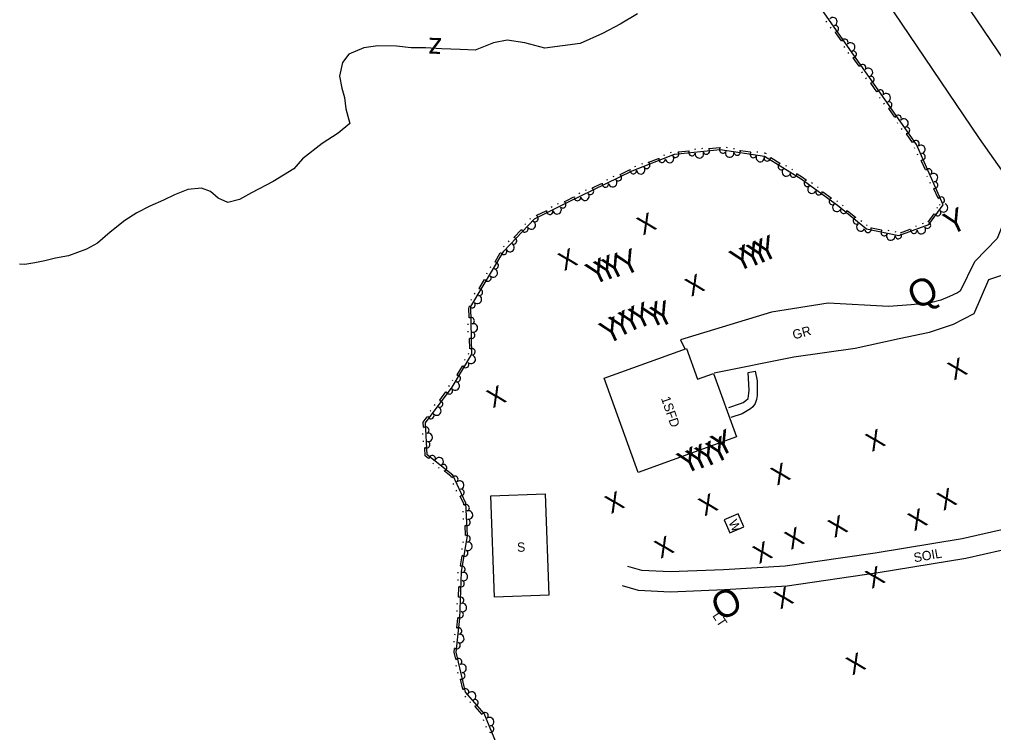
# Model space of a CAD drawing. Extents: x 2030130 to 2036320, y 723205 to 762423.
# Drawn here: x 2032662.3 to 2033049.3, y 761484.7 to 761768 of the extents above; entities that cross this region are included whole.
import ezdxf

# ---------------------------------------------------------------- set-up
doc = ezdxf.new("R2010")
doc.units = 0
for name, color, linetype in [('Draft_Station Cardinal Points', 7, 'Continuous'), ('Draft_Station Labels Major', 7, 'Continuous'), ('Draft_Station Tics Major', 7, 'Continuous'), ('Exist Terrain Model Ground Surface', 7, 'Continuous'), ('Old_Level_15', 7, 'Continuous'), ('Old_Level_23', 7, 'Continuous'), ('Old_Level_28', 7, 'Continuous'), ('Old_Level_29', 7, 'Continuous'), ('Prop Alignment Horizontal', 7, 'Continuous')]:
    doc.layers.add(name, color=color, linetype=linetype)

msp = doc.modelspace()

# ---------------------------------------------------------------- linework, layer by layer
at = {"layer": 'Draft_Station Labels Major'}
msp.add_line((2033036.26, 761660.15), (2033041.96, 761671.86), dxfattribs=at)
for points in [[(2033317.86, 761363.04), (2033290.43, 761403.19), (2033260.47, 761446.88), (2033232.75, 761487.83), (2033204.6, 761528.87), (2033176.73, 761570.42), (2033148.96, 761611.47), (2033120.54, 761652.92), (2033093.45, 761693.44), (2033064.45, 761735.88), (2033037.38, 761775.77), (2033009.06, 761817.74)], [(2032987.95, 761803.12), (2033043.65, 761720.79), (2033056.64, 761702.34), (2033057.8, 761696.58), (2033076.72, 761668.89), (2033082.75, 761662.9), (2033099.45, 761638.44), (2033127.47, 761597.33), (2033155.33, 761556.18), (2033183.52, 761515.12), (2033211.27, 761473.78), (2033239.33, 761432.83), (2033268.78, 761389.51), (2033297.27, 761347.85)], [(2033056.71, 761695.8), (2033050.78, 761681.05), (2033041.96, 761671.86)], [(2033047.49, 761664.65), (2033056.57, 761667.76), (2033074.01, 761668.5)], [(2033033.48, 761646.95), (2033041.61, 761651.18), (2033047.49, 761664.65)], [(2033036.26, 761660.15), (2033034.98, 761659.46), (2033031.83, 761657.97), (2033028.37, 761656.53), (2033024.32, 761655.42), (2033020.58, 761655.09), (2033016.67, 761654.67), (2033007.62, 761654.04), (2032983.56, 761655.29), (2032961.1, 761651.78), (2032924.92, 761640.71), (2032926.73, 761637.14)], [(2032938.32, 761627.58), (2032970.02, 761634.01), (2032994.32, 761637.43), (2033011.86, 761641.33), (2033023.86, 761643.74), (2033033.48, 761646.95)], [(2033094.5, 761577.75), (2033081.76, 761573.32), (2033064.34, 761567.87), (2033036.86, 761561.74), (2033002.27, 761556.02), (2032966.52, 761550.81), (2032942.02, 761549.37), (2032920.85, 761548.52), (2032909.53, 761549.08), (2032903.98, 761550.63)], [(2033097.11, 761570.23), (2033084.26, 761565.76), (2033066.4, 761560.17), (2033038.38, 761553.92), (2033003.49, 761548.15), (2032967.33, 761542.88), (2032942.41, 761541.42), (2032920.81, 761540.55), (2032908.24, 761541.17), (2032901.84, 761542.96)]]:
    msp.add_lwpolyline(points, dxfattribs=at)
at = {"layer": 'Draft_Station Tics Major'}
for points in [[(2032852.15, 761479.7), (2032846.89, 761492.29), (2032839.53, 761500.8), (2032835.8, 761516.7), (2032837.3, 761530.01), (2032837.88, 761548.53), (2032840.35, 761563.07), (2032839.64, 761575.83), (2032834.44, 761586.98), (2032824.33, 761595.03), (2032823.56, 761607.79), (2032834.21, 761621.99), (2032842.05, 761635.05), (2032841.62, 761653.99), (2032854.71, 761675.98), (2032866.89, 761688.81), (2032879.86, 761695.28), (2032905.7, 761707.84), (2032922.57, 761714.44), (2032940.67, 761716.34), (2032958.31, 761713.76), (2032972.94, 761704.72), (2032987.28, 761694.28), (2032998.83, 761684.81), (2033011.7, 761682.14), (2033023.69, 761686.54), (2033029.34, 761694.39), (2033018.75, 761718.29), (2032987.59, 761762.73), (2032957.8, 761805.4)], [(2032983.12, 761766.97), (2032982.89, 761767.31)], [(2032984.76, 761764.62), (2032984.53, 761764.96)], [(2032988.86, 761759.48), (2032986.91, 761762.26), (2032986.51, 761762.84)], [(2032990.18, 761756.89), (2032989.94, 761757.23)], [(2032991.82, 761754.54), (2032991.59, 761754.88)], [(2032995.93, 761749.4), (2032993.57, 761752.76)], [(2032997.24, 761746.82), (2032997, 761747.15)], [(2032998.89, 761744.47), (2032998.65, 761744.8)], [(2033002.99, 761739.33), (2033000.64, 761742.69)], [(2033004.3, 761736.74), (2033004.07, 761737.08)], [(2033005.95, 761734.39), (2033005.72, 761734.73)], [(2033010.05, 761729.26), (2033007.7, 761732.61)], [(2033011.37, 761726.67), (2033011.13, 761727.01)], [(2033013.02, 761724.32), (2033012.78, 761724.65)], [(2033017.12, 761719.18), (2033014.76, 761722.54)], [(2032933.47, 761716.82), (2032933.87, 761716.87)], [(2032936.36, 761716.72), (2032940.44, 761717.15)], [(2032943.14, 761717.22), (2032943.55, 761717.17)], [(2033018.11, 761716.69), (2033017.94, 761717.07)], [(2032918.31, 761714.1), (2032918.7, 761714.25)], [(2032920.99, 761715.15), (2032921.37, 761715.29)], [(2032924.13, 761715.43), (2032928.21, 761715.86)], [(2032930.61, 761716.52), (2032931.02, 761716.57)], [(2032945.98, 761716.81), (2032946.39, 761716.75)], [(2032948.76, 761715.99), (2032952.82, 761715.39)], [(2032955.31, 761715.44), (2032955.72, 761715.38)], [(2032958.16, 761715.02), (2032958.74, 761714.94), (2032959.02, 761714.77)], [(2032960.9, 761713.12), (2032964.39, 761710.97)], [(2033019.27, 761714.07), (2033019.11, 761714.44)], [(2032906.86, 761709.61), (2032907.24, 761709.76)], [(2032909.53, 761710.66), (2032909.91, 761710.81)], [(2032912.35, 761711.33), (2032916.17, 761712.82)], [(2032966.69, 761710.02), (2032967.04, 761709.81)], [(2033022.31, 761708.23), (2033020.64, 761711.98)], [(2032898.23, 761705.58), (2032898.6, 761705.76)], [(2032900.99, 761706.46), (2032904.68, 761708.26)], [(2032969.14, 761708.51), (2032969.48, 761708.3)], [(2032971.36, 761706.65), (2032973.39, 761705.4), (2032974.83, 761704.35)], [(2033023.09, 761705.44), (2033022.93, 761705.82)], [(2032889.93, 761701.08), (2032893.61, 761702.88)], [(2032895.65, 761704.32), (2032896.02, 761704.5)], [(2032977.06, 761703.24), (2032977.39, 761703)], [(2032979.38, 761701.55), (2032979.71, 761701.31)], [(2033024.26, 761702.82), (2033024.09, 761703.19)], [(2032884.58, 761698.94), (2032884.95, 761699.12)], [(2032887.17, 761700.2), (2032887.53, 761700.38)], [(2032981.46, 761699.53), (2032984.77, 761697.11)], [(2033027.29, 761696.98), (2033025.63, 761700.73)], [(2032873.54, 761693.5), (2032873.9, 761693.68)], [(2032876.11, 761694.78), (2032876.47, 761694.96)], [(2032878.86, 761695.69), (2032879.5, 761696.01), (2032882.55, 761697.5)], [(2032987.01, 761696), (2032987.34, 761695.76)], [(2032989.33, 761694.19), (2032989.64, 761693.93)], [(2033028.08, 761694.19), (2033027.91, 761694.57)], [(2032867.85, 761690.21), (2032871.52, 761692.03)], [(2032991.29, 761692.05), (2032994.46, 761689.45)], [(2033023.35, 761687.48), (2033025.75, 761690.81)], [(2033026.85, 761693.05), (2033027.09, 761693.38)], [(2032863.06, 761686.57), (2032863.34, 761686.86)], [(2032865.04, 761688.65), (2032865.32, 761688.95)], [(2032996.62, 761688.21), (2032996.94, 761687.95)], [(2032998.84, 761686.39), (2032999.16, 761686.13)], [(2033018.41, 761685.91), (2033018.79, 761686.05)], [(2033021.1, 761686.9), (2033021.49, 761687.04)], [(2032858.84, 761681.52), (2032861.67, 761684.5)], [(2033000.83, 761685.23), (2033004.85, 761684.4)], [(2033007.34, 761684.3), (2033007.74, 761684.22)], [(2033010.15, 761683.72), (2033010.55, 761683.63)], [(2033012.39, 761683.26), (2033016.24, 761684.68)], [(2032856.57, 761679.72), (2032856.85, 761680.02)], [(2032851.23, 761671.73), (2032853.33, 761675.25)], [(2032854.59, 761677.64), (2032854.88, 761677.94)], [(2032847.94, 761667.01), (2032848.15, 761667.36)], [(2032849.4, 761669.47), (2032849.61, 761669.82)], [(2032844.93, 761661.16), (2032847.03, 761664.68)], [(2032843.11, 761658.9), (2032843.32, 761659.25)], [(2032841.64, 761656.44), (2032841.85, 761656.79)], [(2032840.9, 761649.52), (2032840.8, 761653.62)], [(2032840.55, 761646.64), (2032840.54, 761647.05)], [(2032840.62, 761643.77), (2032840.61, 761644.18)], [(2032841.18, 761637.22), (2032841.09, 761641.32)], [(2032839.17, 761632.64), (2032839.38, 761632.99)], [(2032840.65, 761635.1), (2032840.86, 761635.45)], [(2032836.15, 761626.8), (2032838.26, 761630.32)], [(2032834.32, 761624.55), (2032834.53, 761624.91)], [(2032832.86, 761622.23), (2032833.1, 761622.56)], [(2032829.25, 761616.74), (2032831.71, 761620.02)], [(2032825.48, 761612.39), (2032825.72, 761612.72)], [(2032827.2, 761614.69), (2032827.45, 761615.01)], [(2032822.85, 761606.01), (2032822.73, 761608.04), (2032824.33, 761610.17)], [(2032822.61, 761603.12), (2032822.59, 761603.53)], [(2032822.79, 761600.25), (2032822.76, 761600.66)], [(2032824.81, 761593.61), (2032823.54, 761594.62), (2032823.34, 761597.82)], [(2032826.8, 761591.5), (2032826.48, 761591.76)], [(2032829.04, 761589.71), (2032828.72, 761589.96)], [(2032833.97, 761586.06), (2032833.78, 761586.46), (2032831.22, 761588.5)], [(2032834.81, 761583.28), (2032834.64, 761583.65)], [(2032836.02, 761580.68), (2032835.85, 761581.05)], [(2032838.86, 761575.15), (2032838.83, 761575.63), (2032837.43, 761578.62)], [(2032838.61, 761572.26), (2032838.59, 761572.67)], [(2032838.77, 761569.39), (2032838.75, 761569.8)], [(2032839.52, 761563.05), (2032839.53, 761563.11), (2032839.32, 761566.96)], [(2032838.63, 761560.29), (2032838.7, 761560.69)], [(2032837.46, 761550.92), (2032838.15, 761554.96)], [(2032838.15, 761557.46), (2032838.22, 761557.86)], [(2032836.64, 761547.98), (2032836.65, 761548.39)], [(2032836.55, 761545.11), (2032836.56, 761545.52)], [(2032836.75, 761538.54), (2032836.88, 761542.64)], [(2032836.25, 761535.69), (2032836.27, 761536.1)], [(2032836.16, 761532.82), (2032836.17, 761533.22)], [(2032836.06, 761526.33), (2032836.49, 761530.07), (2032836.5, 761530.34)], [(2032835.33, 761523.53), (2032835.38, 761523.93)], [(2032835.01, 761520.67), (2032835.06, 761521.08)], [(2032835.62, 761513.88), (2032834.97, 761516.65), (2032835.14, 761518.18)], [(2032835.87, 761510.99), (2032835.78, 761511.39)], [(2032836.53, 761508.2), (2032836.44, 761508.6)], [(2032838.43, 761501.9), (2032837.49, 761505.9)], [(2032839.61, 761498.83), (2032839.34, 761499.14)], [(2032841.49, 761496.66), (2032841.22, 761496.97)], [(2032846.09, 761491.96), (2032843.41, 761495.06)], [(2032846.76, 761489.42), (2032846.6, 761489.8)], [(2032847.86, 761486.77), (2032847.71, 761487.15)]]:
    msp.add_lwpolyline(points, dxfattribs=at)
for centre, radius, start, end in [((2032985.51, 761767.14), 1.69, 290.8826, 138.9551), ((2032986.48, 761764.31), 1.3, 265.6873, 106.4839), ((2032990.24, 761758.94), 1.3, 323.4732, 164.2697), ((2032992.56, 761757.06), 1.69, 291.002, 139.0744), ((2032993.54, 761754.24), 1.3, 265.8067, 106.6033), ((2032997.31, 761748.87), 1.3, 323.4732, 164.2697), ((2032999.62, 761746.99), 1.69, 291.002, 139.0744), ((2033000.6, 761744.17), 1.3, 265.8067, 106.6033), ((2033004.37, 761738.79), 1.3, 323.4732, 164.2697), ((2033006.69, 761736.91), 1.69, 291.002, 139.0744), ((2033007.67, 761734.09), 1.3, 265.8067, 106.6033), ((2033011.43, 761728.72), 1.3, 323.4732, 164.2697), ((2033013.75, 761726.84), 1.69, 291.002, 139.0744), ((2033014.73, 761724.02), 1.3, 265.8067, 106.6033), ((2032941.75, 761716.19), 1.3, 132.4304, 333.227), ((2033018.5, 761718.65), 1.3, 323.4732, 164.2697), ((2033020.48, 761716.4), 1.69, 279.8666, 127.939), ((2032920.59, 761712.79), 1.69, 187.3345, 35.407), ((2032922.99, 761714.49), 1.3, 204.4346, 45.2312), ((2032929.52, 761715.17), 1.3, 146.7682, 347.5647), ((2032932.46, 761714.66), 1.69, 171.9634, 20.0359), ((2032935.23, 761715.77), 1.3, 204.4346, 45.2312), ((2032944.47, 761714.96), 1.69, 157.6257, 5.6982), ((2032947.43, 761715.35), 1.3, 190.0969, 30.8935), ((2032953.92, 761714.4), 1.3, 132.4304, 333.227), ((2032956.64, 761713.17), 1.69, 157.6257, 5.6982), ((2032959.42, 761713.07), 1.3, 166.7062, 7.5028), ((2033020.9, 761713.44), 1.3, 254.6713, 95.4678), ((2032909.13, 761708.3), 1.69, 187.3345, 35.407), ((2032911.51, 761710.11), 1.3, 219.8057, 60.6022), ((2032917.62, 761712.5), 1.3, 162.1392, 2.9358), ((2032965, 761709.62), 1.3, 109.0398, 309.8363), ((2032900.24, 761705.19), 1.3, 224.3666, 65.1631), ((2032906.16, 761708.02), 1.3, 162.1392, 2.9358), ((2032967.01, 761707.42), 1.69, 134.235, 342.3075), ((2032969.88, 761706.6), 1.3, 166.7062, 7.5028), ((2033023.55, 761707.44), 1.3, 312.3377, 153.1343), ((2033025.47, 761705.15), 1.69, 279.8666, 127.939), ((2032895.08, 761702.68), 1.3, 166.7001, 7.4967), ((2032898.02, 761703.19), 1.69, 191.8954, 39.9678), ((2032975.34, 761702.97), 1.3, 104.7179, 305.5145), ((2032977.18, 761700.61), 1.69, 129.9132, 337.9857), ((2033025.88, 761702.19), 1.3, 254.6713, 95.4678), ((2032884.02, 761697.3), 1.3, 166.7001, 7.4967), ((2032886.96, 761697.81), 1.69, 191.8954, 39.9678), ((2032889.18, 761699.81), 1.3, 224.3666, 65.1631), ((2032979.98, 761699.59), 1.3, 162.3844, 3.181), ((2032878.12, 761694.41), 1.3, 224.926, 65.7226), ((2032985.29, 761695.73), 1.3, 104.7179, 305.5145), ((2032987.07, 761693.38), 1.69, 126.6347, 334.7072), ((2033028.54, 761696.19), 1.3, 312.3377, 153.1343), ((2033029.48, 761693.18), 1.69, 220.2362, 68.3087), ((2032867.11, 761688.92), 1.3, 224.926, 65.7226), ((2032872.98, 761691.85), 1.3, 167.2596, 8.0561), ((2032875.92, 761692.4), 1.69, 192.4548, 40.5273), ((2032989.81, 761692.2), 1.3, 159.1059, 359.9025), ((2033027.13, 761691.33), 1.3, 195.0409, 35.8375), ((2032865.68, 761686.34), 1.69, 212.4703, 60.5428), ((2032994.89, 761688.04), 1.3, 101.4395, 302.236), ((2032996.59, 761685.59), 1.69, 126.6347, 334.7072), ((2033023.07, 761686.31), 1.3, 218.6129, 59.4095), ((2032863.11, 761684.83), 1.3, 187.275, 28.0716), ((2032999.46, 761684.68), 1.3, 186.6995, 27.496), ((2033005.89, 761683.34), 1.3, 129.033, 329.8296), ((2033008.53, 761681.96), 1.69, 154.2283, 2.3008), ((2033011.51, 761682.18), 1.3, 186.6995, 27.496), ((2033017.68, 761684.33), 1.3, 160.9465, 1.743), ((2033020.65, 761684.55), 1.69, 186.1417, 34.2142), ((2032857.21, 761677.42), 1.69, 212.4703, 60.5428), ((2032858.59, 761680.07), 1.3, 244.9415, 85.7381), ((2032854.66, 761675.89), 1.3, 199.9877, 40.7843), ((2032851.3, 761670.25), 1.3, 257.6542, 98.4507), ((2032850.54, 761667.36), 1.69, 225.183, 73.2555), ((2032848.36, 761665.32), 1.3, 199.9877, 40.7843), ((2032845.01, 761659.68), 1.3, 257.6542, 98.4507), ((2032842.07, 761654.75), 1.3, 199.9877, 40.7843), ((2032844.24, 761656.79), 1.69, 225.183, 73.2555), ((2032841.75, 761648.31), 1.3, 289.7569, 130.5535), ((2032841.88, 761642.57), 1.3, 232.0904, 72.887), ((2032842.63, 761645.46), 1.69, 257.2857, 105.3582), ((2032842.03, 761636.01), 1.3, 289.7569, 130.5535), ((2032839.59, 761630.95), 1.3, 199.7883, 40.5849), ((2032841.78, 761632.99), 1.69, 224.9836, 73.0561), ((2032835.44, 761622.44), 1.69, 224.9836, 73.0561), ((2032836.22, 761625.33), 1.3, 257.4548, 98.2514), ((2032833.1, 761620.51), 1.3, 193.9023, 34.6989), ((2032829.17, 761615.26), 1.3, 251.5688, 92.3653), ((2032828.1, 761612.47), 1.69, 219.0976, 67.1701), ((2032825.72, 761610.67), 1.3, 193.9023, 34.6989), ((2032823.74, 761604.83), 1.3, 291.8945, 132.6911), ((2032824.73, 761602.01), 1.69, 259.4233, 107.4958), ((2032824.09, 761599.1), 1.3, 234.228, 75.0246), ((2032826.28, 761593.48), 1.3, 339.9007, 180.6972), ((2032829.04, 761592.34), 1.69, 307.4295, 155.502), ((2032830.77, 761589.91), 1.3, 282.2342, 123.0308), ((2032835.23, 761585.29), 1.3, 313.4267, 154.2233), ((2032837.19, 761583.03), 1.69, 280.9555, 129.028), ((2032837.66, 761580.08), 1.3, 255.7602, 96.5568), ((2032839.75, 761573.97), 1.3, 291.6309, 132.4275), ((2032840.72, 761571.14), 1.69, 259.1597, 107.2322), ((2032840.07, 761568.23), 1.3, 233.9644, 74.761), ((2032840.12, 761561.7), 1.3, 278.7913, 119.5879), ((2032840.45, 761558.73), 1.69, 246.3201, 94.3926), ((2032839.16, 761556.04), 1.3, 221.1248, 61.9214), ((2032838.06, 761549.57), 1.3, 278.7913, 119.5879), ((2032838.65, 761546.69), 1.69, 254.1732, 102.2457), ((2032837.74, 761543.85), 1.3, 228.9779, 69.7745), ((2032837.53, 761537.29), 1.3, 286.6444, 127.441), ((2032838.26, 761534.39), 1.69, 254.1732, 102.2457), ((2032837.35, 761531.55), 1.3, 228.9779, 69.7745), ((2032836.74, 761525.02), 1.3, 281.9886, 122.7851), ((2032837.23, 761522.07), 1.69, 249.5174, 97.5899), ((2032836.1, 761519.31), 1.3, 224.3221, 65.1187), ((2032836.7, 761512.87), 1.3, 301.6252, 142.4218), ((2032838.15, 761510.26), 1.69, 269.154, 117.2265), ((2032838.01, 761507.28), 1.3, 243.9587, 84.7553), ((2032839.51, 761500.89), 1.3, 301.6252, 142.4218), ((2032841.96, 761499.24), 1.69, 296.8218, 144.8943), ((2032843.22, 761496.53), 1.3, 271.6265, 112.4231), ((2032847.26, 761491.41), 1.3, 311.1149, 151.9115), ((2032849.12, 761489.08), 1.69, 278.6437, 126.7162), ((2032849.47, 761486.11), 1.3, 253.4485, 94.245)]:
    msp.add_arc(centre, radius, start, end, dxfattribs=at)
at = {"layer": 'Exist Terrain Model Ground Surface'}
for points in [[(2032947.18, 761602.14), (2032908.18, 761588.05), (2032894.64, 761625.53), (2032927.28, 761637.32), (2032931.71, 761625.05), (2032938.07, 761627.35)], [(2032849.63, 761578.83), (2032871.2, 761579.56), (2032872.56, 761539.26), (2032850.99, 761538.53)], [(2032947.84, 761571.59), (2032942.36, 761569.19), (2032944.61, 761564.07), (2032950.08, 761566.47)]]:
    msp.add_lwpolyline(points, close=True, dxfattribs=at)
msp.add_lwpolyline([(2032944.13, 761613.92), (2032948.76, 761615.42), (2032949.87, 761615.89), (2032950.96, 761616.69), (2032951.78, 761617.48), (2032952.01, 761618.45), (2032952.16, 761619.56), (2032952.22, 761620.77), (2032951.83, 761627.82), (2032954.62, 761628.34), (2032955.41, 761624.39), (2032955.43, 761622.2), (2032955.46, 761620.19), (2032955.39, 761618.63), (2032955.15, 761617.04), (2032954.63, 761615.42), (2032953.68, 761614.19), (2032952.71, 761613.29), (2032951.41, 761612.55), (2032949.41, 761611.34), (2032944.99, 761609.9)], dxfattribs=at)
at = {"layer": 'Prop Alignment Horizontal'}
msp.add_lwpolyline([(2032907.84, 761770.26), (2032900.95, 761766.12), (2032893.89, 761762.47), (2032885.09, 761758.51), (2032871.05, 761756.59), (2032863.08, 761758.68), (2032856.03, 761759.85), (2032850.61, 761758.69), (2032843.29, 761755.88), (2032837.36, 761756.15), (2032830.01, 761756.4), (2032823.65, 761756.81), (2032817.9, 761756.72), (2032812.02, 761757.45), (2032804.71, 761757.53), (2032799.08, 761756.74), (2032793.2, 761754.23), (2032790.61, 761750.93), (2032789.48, 761745.47), (2032790.38, 761740.7), (2032791.39, 761736.99), (2032791.92, 761732.51), (2032793.52, 761726.75), (2032788.97, 761722.91), (2032782.59, 761718.72), (2032774.77, 761712.66), (2032771.28, 761708.66), (2032763.07, 761703.58), (2032754.41, 761699.19), (2032749.72, 761696.46), (2032745.11, 761695.36), (2032741.22, 761697.08), (2032738.16, 761699.68), (2032734.56, 761701.01), (2032729.23, 761700.47), (2032723.92, 761698.39), (2032719.53, 761696.2), (2032714.11, 761693.88), (2032708.92, 761691.2), (2032704.14, 761688.09), (2032698.35, 761683.56), (2032693.21, 761679.18), (2032688.95, 761676.77), (2032681.68, 761674.16), (2032676.59, 761673.15), (2032672.34, 761672.18), (2032668.38, 761671.33), (2032664.42, 761670.73), (2032662.26, 761670.8)], dxfattribs=at)

# ---------------------------------------------------------------- texts
at = {"layer": 'Draft_Station Cardinal Points'}
msp.add_text('O', height=10.66, rotation=25.7434, dxfattribs=at).set_placement((2032940.48, 761528.83))
at = {"layer": 'Draft_Station Tics Major'}
for s, height, rotation, p in [('Y', 9.02, 25.7438, (2033032.29, 761682.13)), ('X', 7.38, 25.7434, (2032909.96, 761682.13)), ('Y', 9.02, 25.7438, (2032957.36, 761671.13)), ('Y', 9.02, 25.7438, (2032947.47, 761667.39)), ('Y', 9.02, 25.7438, (2032951.62, 761668.75)), ('Y', 9.02, 25.7438, (2032954.43, 761669.85)), ('X', 7.38, 25.7434, (2032878.66, 761667.95)), ('Y', 9.02, 25.7438, (2032893.68, 761663.28)), ('Y', 9.02, 25.7438, (2032896.81, 761664.11)), ('Y', 9.02, 25.7438, (2032902.48, 761665.78)), ('Y', 9.02, 25.7438, (2032890.21, 761662.13)), ('X', 7.38, 25.7434, (2032929.13, 761657.75)), ('Y', 9.02, 25.7438, (2032907.46, 761644.49)), ('Y', 9.02, 25.7438, (2032912.73, 761644.93)), ('Y', 9.02, 25.7438, (2032916.05, 761645.14)), ('Y', 9.02, 25.7438, (2032899.65, 761641.25)), ('Y', 9.02, 25.7438, (2032903.48, 761643.08)), ('Y', 9.02, 25.7438, (2032895.64, 761638.73)), ('X', 7.38, 25.7434, (2033033.51, 761624.51)), ('X', 7.38, 25.7434, (2032850.3, 761613.5)), ('Y', 9.02, 25.7438, (2032940.03, 761593.98)), ('X', 7.38, 25.7434, (2033000.92, 761596.14)), ('Y', 9.02, 25.7438, (2032933.88, 761589.35)), ('Y', 9.02, 25.7438, (2032938.23, 761591.21)), ('Y', 9.02, 25.7438, (2032926.57, 761587.05)), ('Y', 9.02, 25.7438, (2032930.27, 761588.15)), ('X', 7.38, 25.7434, (2032963.2, 761582.74)), ('X', 7.38, 25.7434, (2033029.33, 761572.73)), ('X', 7.38, 25.7434, (2032897.29, 761571.47)), ('X', 7.38, 25.7434, (2032934.42, 761570.54)), ('X', 7.38, 25.7434, (2033017.7, 761564.61)), ('X', 7.38, 25.7434, (2032985.96, 761561.94)), ('X', 7.38, 25.7434, (2032968.72, 761557.22)), ('X', 7.38, 25.7434, (2032916.97, 761553.69)), ('X', 7.38, 25.7434, (2032956.07, 761551.58)), ('X', 7.38, 25.7434, (2033000.84, 761541.73)), ('X', 7.38, 25.7434, (2032964.5, 761533.56)), ('X', 7.38, 25.7434, (2032993.15, 761507.36))]:
    msp.add_text(s, height=height, rotation=rotation, dxfattribs=at).set_placement(p)
at = {"layer": 'Old_Level_15'}
msp.add_text('Q', height=10.66, rotation=25.7434, dxfattribs=at).set_placement((2033018.49, 761652.52))
at = {"layer": 'Old_Level_23'}
for s, rotation, p in [('GR', 15.2105, (2032970.02, 761640.85)), ('SOIL', 9.9232, (2033017.94, 761552.33))]:
    msp.add_text(s, height=3.691, rotation=rotation, dxfattribs=at).set_placement(p)
at = {"layer": 'Old_Level_28'}
for s, height, rotation, p in [('1SFD', 3.691, 289.1734, (2032917.14, 761617.52)), ('W', 3.69, 294.4275, (2032943.91, 761568.31)), ('S', 3.69, 1.9361, (2032860.03, 761556.5))]:
    msp.add_text(s, height=height, rotation=rotation, dxfattribs=at).set_placement(p)
at = {"layer": 'Old_Level_29'}
msp.add_text('LT', height=3.691, rotation=303.0961, dxfattribs=at).set_placement((2032937.49, 761531.16))
at = {"layer": 'Prop Alignment Horizontal'}
msp.add_text('z', height=8.2, rotation=177.9677, dxfattribs=at).set_placement((2032830.21, 761760.58))

doc.saveas('drawing.dxf')
